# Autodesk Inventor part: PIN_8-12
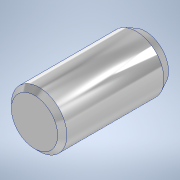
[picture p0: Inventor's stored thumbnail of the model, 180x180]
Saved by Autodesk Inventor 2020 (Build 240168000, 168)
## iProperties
Created: 2023-07
Part Number: PIN_8-12
Material: 알루미늄 6061
Document SubType Name: Modeling
Designer: chae-won
Stock Number: 1
Density: 2.71 g/cm^3
Appearance: 알루미늄 - 평지
Author: chae-won
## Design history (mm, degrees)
sketch "스케치10"
  geometry: C1 r 3 at (0, 0); 1 further point
  constraints: 1 centre point, 1 coincident
  dimensions: "d51" = 6 diameter of C1
extrude "돌출6" new body sketch "스케치10" distance "d52" = 15; taper "d53" = 0 deg
chamfer "모따기2" distance "d54" = 0.5; stored, may be unused: second distance "d55" = 2, angle "d56" = 45 deg
chamfer "모따기3" distance "d57" = 0.5; stored, may be unused: second distance "d58" = 1, angle "d59" = 45 deg
node "솔리드4"
